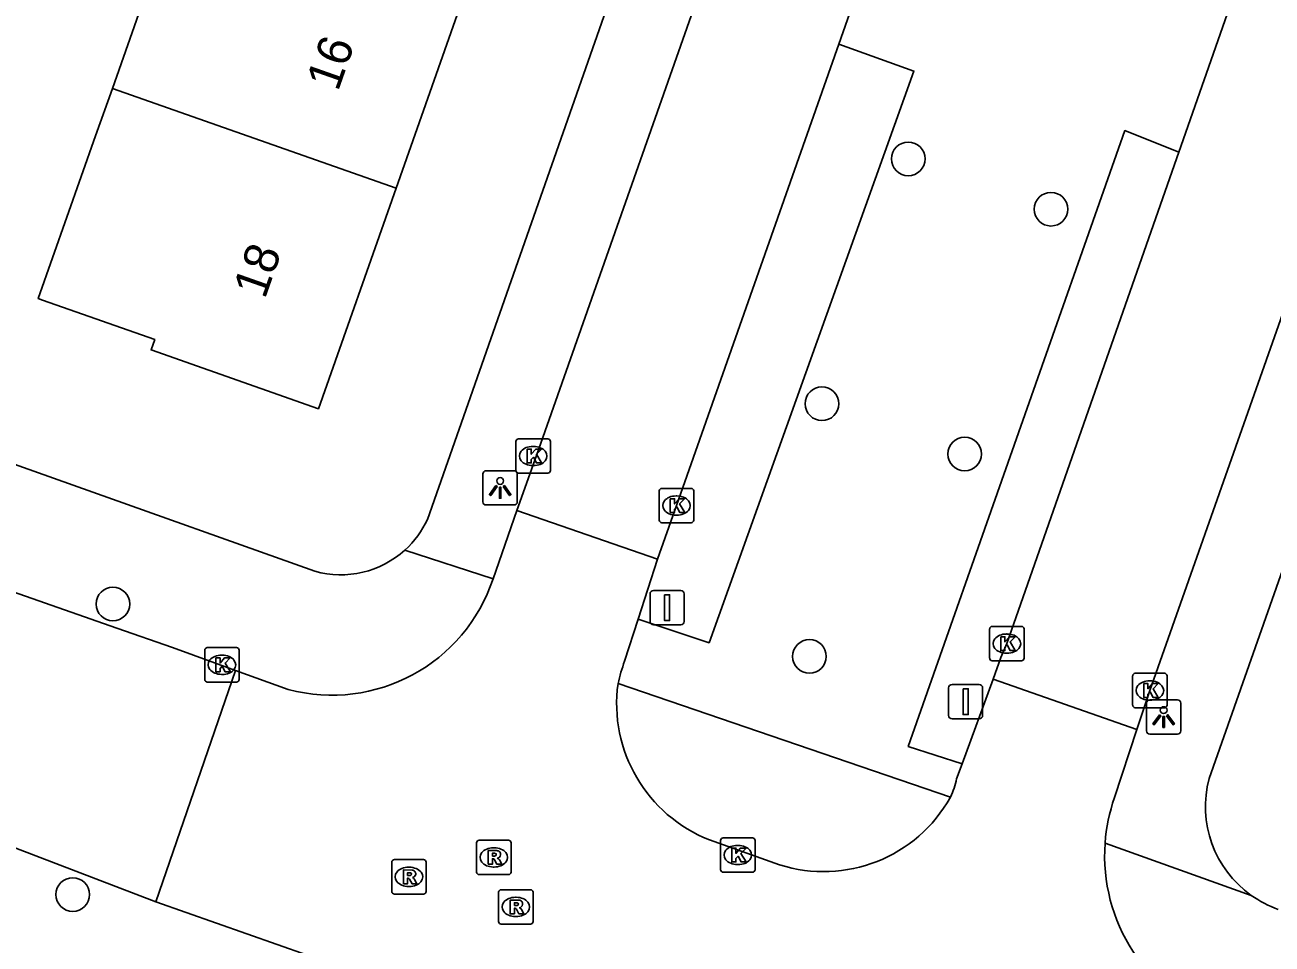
# Model space of a CAD drawing. Extents: x 163268 to 164360, y 381529 to 382285.
# Drawn here: x 163693.84 to 163730.1, y 381720.39 to 381747.12 of the extents above; entities that cross this region are included whole.
import ezdxf

# ---------------------------------------------------------------- set-up
doc = ezdxf.new("R2010")
doc.units = 0
for name, color, linetype in [('IMGEO_Boom', 7, 'Continuous'), ('IMGEO_Groenvoorziening', 7, 'Continuous'), ('IMGEO_Kolk', 7, 'Continuous'), ('IMGEO_Lichtpunt', 7, 'Continuous'), ('IMGEO_Pand', 7, 'Continuous'), ('IMGEO_Pand_nummerreeks', 7, 'Continuous'), ('IMGEO_Rijbaan_lokaal_open', 7, 'Continuous'), ('IMGEO_Rioolput', 7, 'Continuous'), ('IMGEO_Verkeersbordpaal', 7, 'Continuous'), ('IMGEO_Verkeerseiland_open', 7, 'Continuous'), ('IMGEO_Voetpad_open', 7, 'Continuous')]:
    doc.layers.add(name, color=color, linetype=linetype)

msp = doc.modelspace()

# ---------------------------------------------------------------- linework, layer by layer
at = {"layer": 'IMGEO_Boom'}
for centre in [(163719.522, 381743.225), (163723.672, 381741.762), (163717.012, 381736.105), (163721.162, 381734.642), (163696.394, 381730.281), (163716.649, 381728.757), (163695.227, 381721.833)]:
    msp.add_circle(centre, 0.489, dxfattribs=at)
at = {"layer": 'IMGEO_Groenvoorziening'}
for points in [[(163717.502, 381746.561), (163719.685, 381745.78), (163713.728, 381729.156), (163711.665, 381729.842)], [(163721.089, 381725.629), (163719.522, 381726.141), (163725.822, 381744.047), (163727.391, 381743.419)]]:
    msp.add_lwpolyline(points, dxfattribs=at)
at = {"layer": 'IMGEO_Kolk'}
for p, q in [((163708.115, 381734.159), (163708.115, 381735.011)), ((163708.19, 381735.085), (163709.042, 381735.085)), ((163708.603, 381734.865), (163708.628, 381734.865)), ((163709.116, 381735.011), (163709.116, 381734.159)), ((163709.042, 381734.085), (163708.19, 381734.085)), ((163708.626, 381734.305), (163708.601, 381734.305)), ((163712.282, 381732.718), (163712.282, 381733.57)), ((163712.357, 381733.644), (163713.209, 381733.644)), ((163712.77, 381733.424), (163712.795, 381733.424)), ((163713.283, 381733.57), (163713.283, 381732.718)), ((163713.209, 381732.644), (163712.357, 381732.644)), ((163712.793, 381732.864), (163712.768, 381732.864)), ((163721.889, 381728.703), (163721.889, 381729.555)), ((163721.964, 381729.629), (163722.816, 381729.629)), ((163722.377, 381729.409), (163722.402, 381729.409)), ((163722.89, 381729.555), (163722.89, 381728.703)), ((163699.065, 381728.087), (163699.065, 381728.939)), ((163699.14, 381729.013), (163699.992, 381729.013)), ((163700.066, 381728.939), (163700.066, 381728.087)), ((163699.553, 381728.793), (163699.578, 381728.793)), ((163722.816, 381728.629), (163721.964, 381728.629)), ((163722.4, 381728.849), (163722.375, 381728.849)), ((163699.576, 381728.233), (163699.551, 381728.233)), ((163726.122, 381728.266), (163726.974, 381728.266)), ((163699.992, 381728.013), (163699.14, 381728.013)), ((163726.047, 381727.34), (163726.047, 381728.192)), ((163726.535, 381728.046), (163726.56, 381728.046)), ((163727.048, 381728.192), (163727.048, 381727.34)), ((163726.974, 381727.266), (163726.122, 381727.266)), ((163726.558, 381727.486), (163726.533, 381727.486)), ((163714.066, 381722.556), (163714.066, 381723.408)), ((163714.141, 381723.482), (163714.993, 381723.482)), ((163714.554, 381723.262), (163714.579, 381723.262)), ((163715.067, 381723.408), (163715.067, 381722.556)), ((163714.993, 381722.482), (163714.141, 381722.482)), ((163714.577, 381722.702), (163714.552, 381722.702))]:
    msp.add_line(p, q, dxfattribs=at)
for points in [[(163708.115, 381734.159), (163708.115, 381735.011)], [(163708.19, 381735.085), (163709.042, 381735.085)], [(163708.436, 381734.785), (163708.559, 381734.785), (163708.559, 381734.634), (163708.689, 381734.785), (163708.853, 381734.785), (163708.707, 381734.634), (163708.86, 381734.385), (163708.708, 381734.385), (163708.623, 381734.549), (163708.559, 381734.482), (163708.559, 381734.385), (163708.436, 381734.385), (163708.436, 381734.785)], [(163709.116, 381735.011), (163709.116, 381734.159)], [(163709.042, 381734.085), (163708.19, 381734.085)], [(163712.282, 381732.718), (163712.282, 381733.57)], [(163712.357, 381733.644), (163713.209, 381733.644)], [(163712.603, 381733.344), (163712.726, 381733.344), (163712.726, 381733.193), (163712.856, 381733.344), (163713.02, 381733.344), (163712.874, 381733.193), (163713.027, 381732.944), (163712.875, 381732.944), (163712.79, 381733.108), (163712.726, 381733.041), (163712.726, 381732.944), (163712.603, 381732.944), (163712.603, 381733.344)], [(163713.283, 381733.57), (163713.283, 381732.718)], [(163713.209, 381732.644), (163712.357, 381732.644)], [(163721.889, 381728.703), (163721.889, 381729.555)], [(163721.964, 381729.629), (163722.816, 381729.629)], [(163722.21, 381729.329), (163722.333, 381729.329), (163722.333, 381729.178), (163722.463, 381729.329), (163722.627, 381729.329), (163722.481, 381729.178), (163722.634, 381728.929), (163722.482, 381728.929), (163722.397, 381729.093), (163722.333, 381729.026), (163722.333, 381728.929), (163722.21, 381728.929), (163722.21, 381729.329)], [(163722.89, 381729.555), (163722.89, 381728.703)], [(163699.065, 381728.087), (163699.065, 381728.939)], [(163699.14, 381729.013), (163699.992, 381729.013)], [(163700.066, 381728.939), (163700.066, 381728.087)], [(163699.386, 381728.713), (163699.509, 381728.713), (163699.509, 381728.562), (163699.639, 381728.713), (163699.803, 381728.713), (163699.657, 381728.562), (163699.81, 381728.313), (163699.658, 381728.313), (163699.573, 381728.477), (163699.509, 381728.41), (163699.509, 381728.313), (163699.386, 381728.313), (163699.386, 381728.713)], [(163722.816, 381728.629), (163721.964, 381728.629)], [(163726.122, 381728.266), (163726.974, 381728.266)], [(163699.992, 381728.013), (163699.14, 381728.013)], [(163726.047, 381727.34), (163726.047, 381728.192)], [(163726.368, 381727.966), (163726.491, 381727.966), (163726.491, 381727.815), (163726.621, 381727.966), (163726.785, 381727.966), (163726.639, 381727.815), (163726.792, 381727.566), (163726.64, 381727.566), (163726.555, 381727.73), (163726.491, 381727.663), (163726.491, 381727.566), (163726.368, 381727.566), (163726.368, 381727.966)], [(163727.048, 381728.192), (163727.048, 381727.34)], [(163726.974, 381727.266), (163726.122, 381727.266)], [(163714.066, 381722.556), (163714.066, 381723.408)], [(163714.141, 381723.482), (163714.993, 381723.482)], [(163714.387, 381723.182), (163714.51, 381723.182), (163714.51, 381723.031), (163714.64, 381723.182), (163714.804, 381723.182), (163714.658, 381723.031), (163714.811, 381722.782), (163714.659, 381722.782), (163714.574, 381722.946), (163714.51, 381722.879), (163714.51, 381722.782), (163714.387, 381722.782), (163714.387, 381723.182)], [(163715.067, 381723.408), (163715.067, 381722.556)], [(163714.993, 381722.482), (163714.141, 381722.482)]]:
    msp.add_lwpolyline(points, dxfattribs=at)
for centre, start, end in [((163708.192, 381735.009), 91.552, 178.448), ((163708.192, 381735.009), 91.552, 178.448), ((163709.04, 381735.009), 1.552, 88.448), ((163709.04, 381735.009), 1.552, 88.448), ((163708.192, 381734.161), 181.552, 268.448), ((163708.192, 381734.161), 181.552, 268.448), ((163709.04, 381734.161), 271.552, 358.448), ((163709.04, 381734.161), 271.552, 358.448), ((163712.359, 381733.568), 91.552, 178.448), ((163712.359, 381733.568), 91.552, 178.448), ((163713.207, 381733.568), 1.552, 88.448), ((163713.207, 381733.568), 1.552, 88.448), ((163712.359, 381732.72), 181.552, 268.448), ((163712.359, 381732.72), 181.552, 268.448), ((163713.207, 381732.72), 271.552, 358.448), ((163713.207, 381732.72), 271.552, 358.448), ((163721.966, 381729.553), 91.552, 178.448), ((163721.966, 381729.553), 91.552, 178.448), ((163722.814, 381729.553), 1.552, 88.448), ((163722.814, 381729.553), 1.552, 88.448), ((163699.142, 381728.937), 91.552, 178.448), ((163699.142, 381728.937), 91.552, 178.448), ((163699.99, 381728.937), 1.552, 88.448), ((163699.99, 381728.937), 1.552, 88.448), ((163721.966, 381728.705), 181.552, 268.448), ((163721.966, 381728.705), 181.552, 268.448), ((163722.814, 381728.705), 271.552, 358.448), ((163722.814, 381728.705), 271.552, 358.448), ((163726.124, 381728.19), 91.552, 178.448), ((163726.124, 381728.19), 91.552, 178.448), ((163726.972, 381728.19), 1.552, 88.448), ((163726.972, 381728.19), 1.552, 88.448), ((163699.142, 381728.089), 181.552, 268.448), ((163699.142, 381728.089), 181.552, 268.448), ((163699.99, 381728.089), 271.552, 358.448), ((163699.99, 381728.089), 271.552, 358.448), ((163726.124, 381727.342), 181.552, 268.448), ((163726.124, 381727.342), 181.552, 268.448), ((163726.972, 381727.342), 271.552, 358.448), ((163726.972, 381727.342), 271.552, 358.448), ((163714.143, 381723.406), 91.552, 178.448), ((163714.143, 381723.406), 91.552, 178.448), ((163714.991, 381723.406), 1.552, 88.448), ((163714.991, 381723.406), 1.552, 88.448), ((163714.143, 381722.558), 181.552, 268.448), ((163714.143, 381722.558), 181.552, 268.448), ((163714.991, 381722.558), 271.552, 358.448), ((163714.991, 381722.558), 271.552, 358.448)]:
    msp.add_arc(centre, 0.0765, start, end, dxfattribs=at)
for centre, major_axis, ratio, start_param, end_param in [((163708.602, 381734.585), (-0.387, 0.002), 0.722429, 4.712389, 7.853982), ((163708.627, 381734.585), (-0.39, 0.002), 0.717154, 1.570796, 4.712389), ((163712.769, 381733.144), (-0.387, 0.002), 0.722429, 4.712389, 7.853982), ((163712.794, 381733.144), (-0.39, 0.002), 0.717154, 1.570796, 4.712389), ((163722.376, 381729.129), (-0.387, 0.002), 0.722429, 4.712389, 7.853982), ((163722.401, 381729.129), (-0.39, 0.002), 0.717154, 1.570796, 4.712389), ((163699.552, 381728.513), (-0.387, 0.002), 0.722429, 4.712389, 7.853982), ((163699.577, 381728.513), (-0.39, 0.002), 0.717154, 1.570796, 4.712389), ((163726.534, 381727.766), (-0.387, 0.002), 0.722429, 4.712389, 7.853982), ((163726.559, 381727.766), (-0.39, 0.002), 0.717154, 1.570796, 4.712389), ((163714.553, 381722.982), (-0.387, 0.002), 0.722429, 4.712389, 7.853982), ((163714.578, 381722.982), (-0.39, 0.002), 0.717154, 1.570796, 4.712389)]:
    msp.add_ellipse(centre, major_axis=major_axis, ratio=ratio, start_param=start_param, end_param=end_param, dxfattribs=at)
at = {"layer": 'IMGEO_Lichtpunt'}
for p, q in [((163707.156, 381734.062), (163707.156, 381733.255)), ((163707.156, 381734.062), (163707.156, 381733.255)), ((163708.058, 381734.157), (163707.25, 381734.157)), ((163708.058, 381734.157), (163707.25, 381734.157)), ((163708.152, 381733.255), (163708.152, 381734.062)), ((163708.152, 381733.255), (163708.152, 381734.062)), ((163707.25, 381733.161), (163708.058, 381733.161)), ((163707.25, 381733.161), (163708.058, 381733.161)), ((163727.351, 381727.493), (163726.543, 381727.493)), ((163727.351, 381727.493), (163726.543, 381727.493)), ((163726.449, 381727.398), (163726.449, 381726.591)), ((163726.449, 381727.398), (163726.449, 381726.591)), ((163727.445, 381726.591), (163727.445, 381727.398)), ((163727.445, 381726.591), (163727.445, 381727.398)), ((163726.543, 381726.497), (163727.351, 381726.497)), ((163726.543, 381726.497), (163727.351, 381726.497))]:
    msp.add_line(p, q, dxfattribs=at)
for points in [[(163707.53, 381733.726), (163707.569, 381733.698), (163707.381, 381733.436), (163707.343, 381733.463), (163707.53, 381733.726)], [(163707.632, 381733.678), (163707.679, 381733.678), (163707.679, 381733.356), (163707.632, 381733.356), (163707.632, 381733.678)], [(163707.742, 381733.698), (163707.78, 381733.725), (163707.967, 381733.463), (163707.928, 381733.435), (163707.742, 381733.698)], [(163726.823, 381727.062), (163726.862, 381727.034), (163726.674, 381726.772), (163726.636, 381726.799), (163726.823, 381727.062)], [(163726.925, 381727.014), (163726.972, 381727.014), (163726.972, 381726.692), (163726.925, 381726.692), (163726.925, 381727.014)], [(163727.035, 381727.034), (163727.073, 381727.061), (163727.26, 381726.799), (163727.221, 381726.771), (163727.035, 381727.034)]]:
    msp.add_lwpolyline(points, dxfattribs=at)
for centre in [(163707.655, 381733.86), (163726.948, 381727.196)]:
    msp.add_circle(centre, 0.0994, dxfattribs=at)
for centre, start, end in [((163707.25, 381734.062), 90, 180), ((163707.25, 381734.062), 90, 180), ((163708.058, 381734.062), 0, 90), ((163708.058, 381734.062), 0, 90), ((163707.25, 381733.255), 180, 270), ((163707.25, 381733.255), 180, 270), ((163708.058, 381733.255), 270, 0), ((163708.058, 381733.255), 270, 360), ((163726.543, 381727.398), 90, 180), ((163726.543, 381727.398), 90, 180), ((163727.351, 381727.398), 0, 90), ((163727.351, 381727.398), 0, 90), ((163726.543, 381726.591), 180, 270), ((163726.543, 381726.591), 180, 270), ((163727.351, 381726.591), 270, 0), ((163727.351, 381726.591), 270, 360)]:
    msp.add_arc(centre, 0.0946, start, end, dxfattribs=at)
at = {"layer": 'IMGEO_Pand'}
for points in [[(163698.468, 381751.206), (163698.043, 381750), (163696.378, 381745.273)], [(163704.627, 381742.372), (163706.716, 381748.305)], [(163696.378, 381745.273), (163695.893, 381743.897), (163694.224, 381739.161), (163694.351, 381739.117), (163694.543, 381739.049), (163697.61, 381737.97), (163697.504, 381737.67), (163702.369, 381735.958), (163704.627, 381742.372)], [(163704.627, 381742.372), (163696.378, 381745.273)]]:
    msp.add_lwpolyline(points, dxfattribs=at)
at = {"layer": 'IMGEO_Rijbaan_lokaal_open'}
for points in [[(163708.144, 381732.996), (163708.709, 381734.601), (163714.691, 381751.607), (163721.738, 381771.833), (163728.396, 381790.753), (163728.949, 381792.401)], [(163747.057, 381785.97), (163746.635, 381784.85), (163745.593, 381781.889), (163739.668, 381765.046), (163732.844, 381745.637), (163726.548, 381727.766), (163726.164, 381726.628)], [(163717.502, 381746.561), (163718.765, 381750.154), (163725.865, 381770.395), (163727.899, 381776.195)], [(163737.935, 381773.39), (163735.506, 381766.493), (163728.863, 381747.625), (163727.391, 381743.419)], [(163712.226, 381731.582), (163712.783, 381733.144), (163717.502, 381746.561)], [(163654.429, 381744.322), (163658.899, 381742.752), (163696.505, 381729.58), (163698.123, 381729.013), (163699.958, 381728.351)], [(163727.391, 381743.419), (163722.39, 381729.129), (163722.214, 381728.721), (163721.988, 381728.099)], [(163707.447, 381731.015), (163708.144, 381732.996)], [(163708.144, 381732.996), (163712.226, 381731.582)], [(163712.226, 381731.582), (163711.665, 381729.842)], [(163711.665, 381729.842), (163711.27, 381728.617)], [(163697.64, 381721.621), (163699.958, 381728.351)], [(163699.958, 381728.351), (163701.495, 381727.796)], [(163697.64, 381721.621), (163693.576, 381723.182), (163679.468, 381728.152)], [(163721.089, 381725.629), (163721.988, 381728.099)], [(163721.988, 381728.099), (163726.164, 381726.628)], [(163726.164, 381726.628), (163725.519, 381724.651)], [(163720.928, 381725.202), (163721.089, 381725.629)], [(163713.74, 381723.424), (163715.779, 381722.701)], [(163705.584, 381718.826), (163697.64, 381721.621)]]:
    msp.add_lwpolyline(points, dxfattribs=at)
for centre, radius, start, end in [((163702.765, 381732.561), 4.931, 255.0789, 341.7325), ((163717.822, 381726.378), 6.924, 161.1309, 166.7219), ((163715.303, 381727.387), 4.26, 172.1579, 248.4741), ((163718.75, 381725.643), 2.222, 333.9282, 348.5618), ((163717.066, 381726.708), 4.209, 252.1966, 330.9719), ((163730.378, 381722.959), 5.146, 160.7982, 175.8833), ((163730.36, 381722.961), 5.127, 175.8918, 249.7129)]:
    msp.add_arc(centre, radius, start, end, dxfattribs=at)
at = {"layer": 'IMGEO_Rioolput'}
for p, q in [((163706.97, 381722.487), (163706.97, 381723.339)), ((163707.045, 381723.413), (163707.897, 381723.413)), ((163707.458, 381723.193), (163707.483, 381723.193)), ((163707.971, 381723.339), (163707.971, 381722.487)), ((163704.578, 381722.847), (163705.43, 381722.847)), ((163704.503, 381721.921), (163704.503, 381722.773)), ((163704.991, 381722.627), (163705.016, 381722.627)), ((163705.504, 381722.773), (163705.504, 381721.921)), ((163707.897, 381722.413), (163707.045, 381722.413)), ((163707.481, 381722.633), (163707.456, 381722.633)), ((163705.014, 381722.067), (163704.989, 381722.067)), ((163705.43, 381721.847), (163704.578, 381721.847)), ((163707.611, 381721.047), (163707.611, 381721.899)), ((163707.686, 381721.973), (163708.538, 381721.973)), ((163708.099, 381721.753), (163708.124, 381721.753)), ((163708.612, 381721.899), (163708.612, 381721.047)), ((163708.538, 381720.973), (163707.686, 381720.973)), ((163708.122, 381721.193), (163708.097, 381721.193))]:
    msp.add_line(p, q, dxfattribs=at)
for points in [[(163706.97, 381722.487), (163706.97, 381723.339)], [(163707.045, 381723.413), (163707.897, 381723.413)], [(163707.971, 381723.339), (163707.971, 381722.487)], [(163704.578, 381722.847), (163705.43, 381722.847)], [(163707.559, 381723.111), (163707.307, 381723.113), (163707.307, 381722.713)], [(163707.307, 381722.713), (163707.431, 381722.713), (163707.431, 381722.875), (163707.442, 381722.875)], [(163707.485, 381723.032), (163707.431, 381723.032), (163707.431, 381722.951)], [(163707.431, 381722.951), (163707.483, 381722.951)], [(163707.489, 381722.846), (163707.56, 381722.713), (163707.7, 381722.713), (163707.635, 381722.839)], [(163704.503, 381721.921), (163704.503, 381722.773)], [(163705.092, 381722.545), (163704.84, 381722.547), (163704.84, 381722.147)], [(163705.018, 381722.466), (163704.964, 381722.466), (163704.964, 381722.385)], [(163705.504, 381722.773), (163705.504, 381721.921)], [(163707.897, 381722.413), (163707.045, 381722.413)], [(163704.84, 381722.147), (163704.964, 381722.147), (163704.964, 381722.309), (163704.975, 381722.309)], [(163704.964, 381722.385), (163705.016, 381722.385)], [(163705.022, 381722.28), (163705.093, 381722.147), (163705.233, 381722.147), (163705.168, 381722.273)], [(163705.43, 381721.847), (163704.578, 381721.847)], [(163707.611, 381721.047), (163707.611, 381721.899)], [(163707.686, 381721.973), (163708.538, 381721.973)], [(163708.612, 381721.899), (163708.612, 381721.047)], [(163708.2, 381721.671), (163707.948, 381721.673), (163707.948, 381721.273)], [(163707.948, 381721.273), (163708.072, 381721.273), (163708.072, 381721.435), (163708.083, 381721.435)], [(163708.126, 381721.592), (163708.072, 381721.592), (163708.072, 381721.511)], [(163708.072, 381721.511), (163708.124, 381721.511)], [(163708.13, 381721.406), (163708.201, 381721.273), (163708.341, 381721.273), (163708.276, 381721.399)], [(163708.538, 381720.973), (163707.686, 381720.973)]]:
    msp.add_lwpolyline(points, dxfattribs=at)
for centre, radius, start, end in [((163707.047, 381723.337), 0.0765, 91.552, 178.448), ((163707.047, 381723.337), 0.0765, 91.552, 178.448), ((163707.895, 381723.337), 0.0765, 1.552, 88.448), ((163707.895, 381723.337), 0.0765, 1.552, 88.448), ((163704.58, 381722.771), 0.0765, 91.552, 178.448), ((163704.58, 381722.771), 0.0765, 91.552, 178.448), ((163705.428, 381722.771), 0.0765, 1.552, 88.448), ((163705.428, 381722.771), 0.0765, 1.552, 88.448), ((163707.441, 381722.822), 0.0533, 26.0293, 88.6989), ((163707.467, 381723.14), 0.19, 274.7715, 282.9687), ((163707.491, 381722.936), 0.0964, 77.0061, 93.1865), ((163707.505, 381722.993), 0.0378, 276.6634, 79.6772), ((163707.558, 381723.001), 0.109, 350.3612, 89.416), ((163707.556, 381723.001), 0.112, 277.5842, 350.9817), ((163707.54, 381722.786), 0.108, 29.5134, 73.7905), ((163705.024, 381722.37), 0.0964, 77.0061, 93.1865), ((163705.038, 381722.427), 0.0378, 276.6634, 79.6772), ((163705.091, 381722.435), 0.109, 350.3612, 89.416), ((163705.089, 381722.435), 0.112, 277.5842, 350.9817), ((163707.047, 381722.489), 0.0765, 181.552, 268.448), ((163707.047, 381722.489), 0.0765, 181.552, 268.448), ((163707.895, 381722.489), 0.0765, 271.552, 358.448), ((163707.895, 381722.489), 0.0765, 271.552, 358.448), ((163704.974, 381722.256), 0.0533, 26.0293, 88.6989), ((163705, 381722.574), 0.19, 274.7715, 282.9687), ((163705.073, 381722.22), 0.108, 29.5134, 73.7905), ((163704.58, 381721.923), 0.0765, 181.552, 268.448), ((163704.58, 381721.923), 0.0765, 181.552, 268.448), ((163705.428, 381721.923), 0.0765, 271.552, 358.448), ((163705.428, 381721.923), 0.0765, 271.552, 358.448), ((163707.688, 381721.897), 0.0765, 91.552, 178.448), ((163707.688, 381721.897), 0.0765, 91.552, 178.448), ((163708.536, 381721.897), 0.0765, 1.552, 88.448), ((163708.536, 381721.897), 0.0765, 1.552, 88.448), ((163708.082, 381721.382), 0.0533, 26.0293, 88.6989), ((163708.108, 381721.7), 0.19, 274.7715, 282.9687), ((163708.132, 381721.496), 0.0964, 77.0061, 93.1865), ((163708.146, 381721.553), 0.0378, 276.6634, 79.6772), ((163708.199, 381721.561), 0.109, 350.3612, 89.416), ((163708.197, 381721.561), 0.112, 277.5842, 350.9817), ((163708.181, 381721.346), 0.108, 29.5134, 73.7905), ((163707.688, 381721.049), 0.0765, 181.552, 268.448), ((163707.688, 381721.049), 0.0765, 181.552, 268.448), ((163708.536, 381721.049), 0.0765, 271.552, 358.448), ((163708.536, 381721.049), 0.0765, 271.552, 358.448)]:
    msp.add_arc(centre, radius, start, end, dxfattribs=at)
for centre, major_axis, ratio, start_param, end_param in [((163707.457, 381722.913), (-0.387, 0.002), 0.722429, 4.712389, 7.853982), ((163707.482, 381722.913), (-0.39, 0.002), 0.717154, 1.570796, 4.712389), ((163704.99, 381722.347), (-0.387, 0.002), 0.722429, 4.712389, 7.853982), ((163705.015, 381722.347), (-0.39, 0.002), 0.717154, 1.570796, 4.712389), ((163708.098, 381721.473), (-0.387, 0.002), 0.722429, 4.712389, 7.853982), ((163708.123, 381721.473), (-0.39, 0.002), 0.717154, 1.570796, 4.712389)]:
    msp.add_ellipse(centre, major_axis=major_axis, ratio=ratio, start_param=start_param, end_param=end_param, dxfattribs=at)
at = {"layer": 'IMGEO_Verkeersbordpaal'}
for p, q in [((163712.014, 381729.773), (163712.014, 381730.573)), ((163712.014, 381730.573), (163712.014, 381729.773)), ((163712.114, 381730.673), (163712.904, 381730.673)), ((163712.904, 381730.673), (163712.114, 381730.673)), ((163713.004, 381730.573), (163713.004, 381729.773)), ((163713.004, 381729.773), (163713.004, 381730.573)), ((163712.904, 381729.673), (163712.114, 381729.673)), ((163712.114, 381729.673), (163712.904, 381729.673)), ((163720.795, 381727.942), (163721.585, 381727.942)), ((163721.585, 381727.942), (163720.795, 381727.942)), ((163720.695, 381727.042), (163720.695, 381727.842)), ((163720.695, 381727.842), (163720.695, 381727.042)), ((163721.685, 381727.842), (163721.685, 381727.042)), ((163721.685, 381727.042), (163721.685, 381727.842)), ((163721.585, 381726.942), (163720.795, 381726.942)), ((163720.795, 381726.942), (163721.585, 381726.942))]:
    msp.add_line(p, q, dxfattribs=at)
for points in [[(163712.434, 381730.548), (163712.584, 381730.548), (163712.584, 381729.798), (163712.434, 381729.798), (163712.434, 381730.548)], [(163721.115, 381727.817), (163721.265, 381727.817), (163721.265, 381727.067), (163721.115, 381727.067), (163721.115, 381727.817)]]:
    msp.add_lwpolyline(points, dxfattribs=at)
for centre, start, end in [((163712.114, 381730.573), 90, 180), ((163712.114, 381730.573), 90, 180), ((163712.904, 381730.573), 0, 90), ((163712.904, 381730.573), 360, 90), ((163712.114, 381729.773), 180, 270), ((163712.114, 381729.773), 180, 270), ((163712.904, 381729.773), 270, 0), ((163712.904, 381729.773), 270, 0), ((163720.795, 381727.842), 90, 180), ((163720.795, 381727.842), 90, 180), ((163721.585, 381727.842), 0, 90), ((163721.585, 381727.842), 360, 90), ((163720.795, 381727.042), 180, 270), ((163720.795, 381727.042), 180, 270), ((163721.585, 381727.042), 270, 0), ((163721.585, 381727.042), 270, 0)]:
    msp.add_arc(centre, 0.1, start, end, dxfattribs=at)
at = {"layer": 'IMGEO_Verkeerseiland_open'}
msp.add_lwpolyline([(163720.746, 381724.666), (163711.083, 381727.968)], dxfattribs=at)
at = {"layer": 'IMGEO_Voetpad_open'}
for points in [[(163727.346, 381794.905), (163711.594, 381750), (163705.54, 381732.742)], [(163728.272, 381725.208), (163736.998, 381750), (163750.011, 381786.97)], [(163702.269, 381731.232), (163681.177, 381738.741)], [(163707.447, 381731.015), (163704.886, 381731.851)], [(163725.246, 381723.328), (163729.497, 381721.808)]]:
    msp.add_lwpolyline(points, dxfattribs=at)
for centre, radius, start, end in [((163703.018, 381733.908), 2.779, 312.2497, 335.1925), ((163703.018, 381733.909), 2.78, 254.3785, 312.2367), ((163731.328, 381724.388), 3.164, 164.9814, 234.6462), ((163731.33, 381724.394), 3.17, 234.6786, 250.6813)]:
    msp.add_arc(centre, radius, start, end, dxfattribs=at)

# ---------------------------------------------------------------- texts
at = {"layer": 'IMGEO_Pand_nummerreeks'}
for s, rotation, p in [('16', 70.6035, (163702.937, 381745.16)), ('18', 70.6056, (163700.812, 381739.124))]:
    msp.add_text(s, height=1, rotation=rotation, dxfattribs=at).set_placement(p)

doc.saveas('drawing.dxf')
